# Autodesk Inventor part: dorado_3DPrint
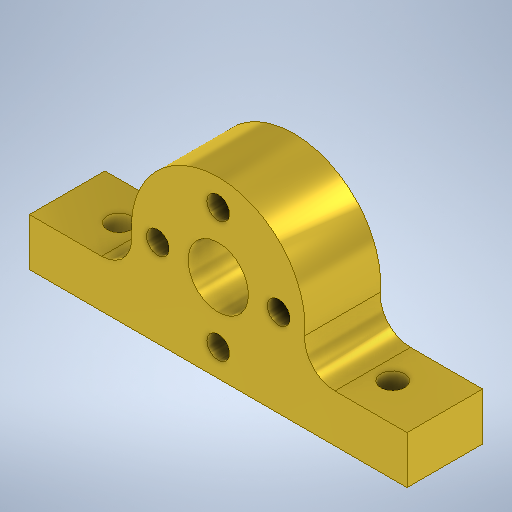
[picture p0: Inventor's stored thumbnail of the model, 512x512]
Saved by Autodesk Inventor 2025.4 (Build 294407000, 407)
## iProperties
Created: 2026-04
Part Number: dorado_3DPrint
Material: Generic
Document SubType Name: Modeling
Designer: PC
Density: 1 g/cm^3
Appearance: Default
Author: PC
Part Number: dorado
Material: Gold
Density: 19.3 g/cm^3
Appearance: Metal 2400F Hot
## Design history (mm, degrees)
sketch "Sketch1"
  geometry: L1 (-25, -11.6)-(25, -11.6); L2 (25, -11.6)-(25, -5.3); L3 (-5.773, 11.5)-(6.907, 11.5); L4 (-25, -11.6)-(-25, -5.3); L5 (-25, -5.3)-(-15.445, -5.3); L6 (15.445, -5.3)-(25, -5.3); C1 r 4 at (0, 0); A1 r 11.5 centre (0, 0) between (11.459, -0.965) and (-11.459, -0.965); A2 r 4 centre (-15.445, -1.3) between (-15.445, -5.3) and (-11.459, -0.965); A3 r 4 centre (15.445, -1.3) between (11.459, -0.965) and (15.445, -5.3); 2 further points
  constraints: 12 end point, 6 point on circle, 5 tangent, 4 centre point, 2 coincident, 2 horizontal, 2 perpendicular, 1 collinear, 1 midpoint, 1 vertical
  dimensions: "d0" = 23 diameter of A1; "d1" = 50 distance of L1.start L1.end; "d2" = 6.3 distance of L1.end L2.end; "d3" = 8 diameter of C1; "d4" = 25 distance from line of L2 point (0, 0); "d5" = 23.1 distance between parallel lines of L1 L3; "d6" = 8 diameter of A2; "d7" = 8 diameter of A3; "d33" = 6.3 distance from line of L1 point (-20.223, -5.3)
extrude "Extrusion1" new body sketch "Sketch1" distance "d8" = 10; taper "d9" = 0 deg
sketch "Sketch2"
  geometry: C1 r 11.5 at (0, 0); C2 r 5 at (0, 0); C3 r 4 at (0, 0); C4 r 4 at (0, 0); 1 further point
  constraints: 4 centre point, 4 coincident, 1 concentric
  dimensions: "d10" = 10 diameter of C2
extrude "Extrusion2" join sketch "Sketch2" distance "d11" = 4; taper "d12" = 0 deg
extrude "Extrusion3" join sketch "Sketch2" distance "d13" = 5; taper "d14" = 0 deg
sketch "Sketch3"
  geometry: C1 r 1.5 at (0, 8); C2 r 1.5 at (0, -8); C3 r 1.5 at (8, 0); C4 r 1.5 at (-8, 0); 1 further point
  constraints: 4 centre point
  dimensions: "d15" = 3 diameter of C1; "d16" = 3 diameter of C2; "d17" = 3 diameter of C3; "d18" = 3 diameter of C4; "d19" = 8 distance of point (0, 0) C4.centre; "d20" = 8 distance of C3.centre point (0, 0); "d21" = 8 distance of point (0, 0) C1.centre; "d22" = 8 distance of point (0, 0) C2.centre
extrude "Extrusion4" cut sketch "Sketch3" extent not by distance; stored distance "d23" = 0; taper "d24" = 0 deg
sketch "Sketch4"
  geometry: L1 (8.5, -2.584)-(8.5, -7.824); L2 (41.5, -2.584)-(41.5, -8.613); L3 (0, 0)-(0, -10) reference; L4 (50, 0)-(50, -10) reference; L5 (9.555, 0)-(0, 0) reference; C1 r 1.6 at (6.9, -5); C2 r 1.6 at (43.1, -5); 1 further point
  constraints: 4 end point, 2 centre point, 2 tangent, 2 vertical, 1 horizontal alignment
  dimensions: "d25" = 3.2 diameter of C1; "d26" = 3.2 diameter of C2; "d27" = 33 distance between parallel lines of L2 L1; "d28" = 50 distance between parallel lines of L3 L4 (derived); "d29" = 8.5 distance between parallel lines of L4 L2; "d30" = 5 distance from line of L5 C1.centre
extrude "Extrusion5" cut sketch "Sketch4" distance "d31" = 10; taper "d32" = 0 deg
sketch "Sketch5"
  geometry: C1 r 19.918 at (0, 0); 1 further point
  constraints: 1 centre point, 1 coincident
extrude "Extrusion6" cut sketch "Sketch5" distance "d34" = 5; taper "d35" = 0 deg
body "Solid1"
